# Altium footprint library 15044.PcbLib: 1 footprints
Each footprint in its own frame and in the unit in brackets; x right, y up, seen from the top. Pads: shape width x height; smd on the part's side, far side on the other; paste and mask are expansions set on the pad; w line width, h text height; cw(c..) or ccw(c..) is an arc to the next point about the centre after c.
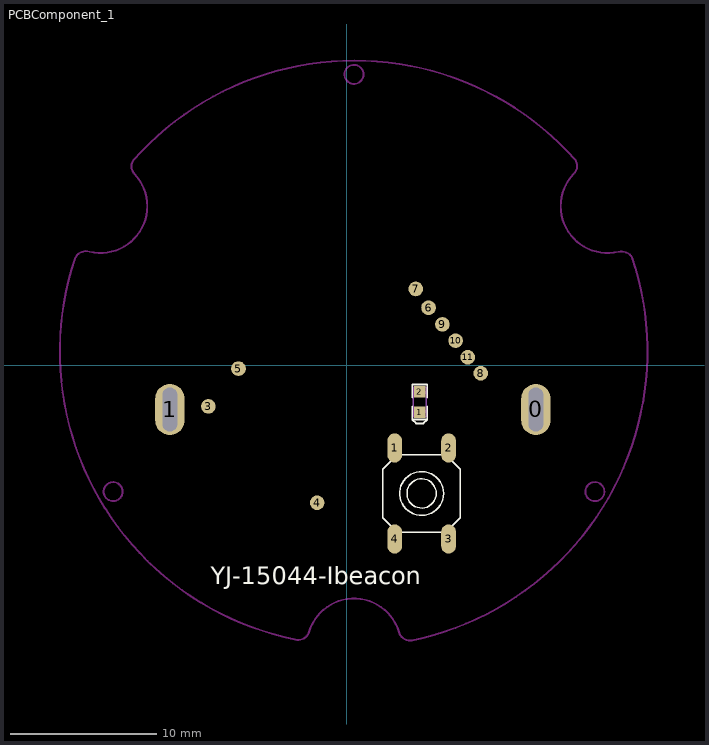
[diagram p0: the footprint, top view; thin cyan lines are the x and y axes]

## PCBComponent_1 [mm]
pads (17):
  oval 2x3.5 hole 1 slot 3 at 90 deg: 0(12.907,-3.027) 1(-12.093,-3.027)
  oval 1x2 smd: 1(3.266,-5.653) 2(6.946,-5.653) 3(6.946,-11.873) 4(3.266,-11.873)
  rect 0.813x0.762 smd: 1(4.978,-3.213) 2(4.978,-1.816)
  round 1 smd: 3(-9.459,-2.817) 4(-2.029,-9.397) 5(-7.402,-0.232) 6(5.578,3.926) 7(4.708,5.206) 8(9.148,-0.554) 9(6.528,2.786) 10(7.428,1.676) 11(8.258,0.536)
Top Overlay:
  circle w0.1: c5.106,-8.763 r1
  circle w0.1: c5.106,-8.763 r1.5
  lines w0.1: 2.456,-10.413 3.456,-11.413 6.756,-11.413 7.756,-10.413 7.756,-7.113 6.756,-6.113 3.456,-6.113 2.456,-7.113 2.456,-10.413
  lines w0.127: 4.47,-2.832 4.47,-3.721 ; 4.47,-2.197 4.47,-1.308 5.486,-1.308 5.486,-2.197 ; 5.486,-2.832 5.486,-3.721 ; 4.47,-3.721 5.486,-3.721 ; 4.47,-3.721 4.724,-3.975 5.232,-3.975 5.486,-3.721
  text "YJ-15044-Ibeacon" at -9.309,-14.967 h1.2
Keep-Out Layer:
  circle w0.127: c-15.967,-8.637 r0.65
  circle w0.127: c0.488,19.863 r0.65
  circle w0.127: c16.942,-8.637 r0.65
  lines w0.127: -14.569,14.023 ccw(c-13.959,13.583) -14.496,13.057 ; -14.568,14.022 cw(c0.521,0.653) 15.593,14.039 cw(c14.981,13.613) 15.481,13.059 ccw(c17.808,10.863) 18.546,7.749 ; -14.506,13.059 cw(c-16.833,10.863) -17.571,7.749 ccw(c-17.819,6.983) -18.572,7.268 ccw(c0.441,0.913) -3.539,-18.735 ; -3.539,-18.737 ccw(c-3.319,-17.997) -2.578,-18.214 ; -2.578,-18.219 cw(c0.488,-19.137) 3.553,-18.219 ccw(c4.331,-18.007) 4.456,-18.803 ccw(c0.351,0.953) 19.487,7.355 ccw(c18.741,6.903) 18.539,7.752
Mechanical 7:
  lines w0.1: 4.54,-3.215 5.417,-3.215 ; 4.54,-3.115 5.417,-3.115 ; 4.54,-1.915 5.417,-1.915 ; 4.54,-1.815 5.417,-1.815 ; 4.54,-3.515 4.54,-1.515 5.417,-1.515 5.417,-3.515 4.54,-3.515
  text "LED_G" at 5.103,-3.015 h0.3
3D body: height 0.6, standoff 0, extent 4.578,-3.318 5.378,-1.698
3D body: height 1, standoff 0, extent 2.439,-11.43 7.773,-6.096
3D body: height 0.2, standoff 0, extent 6.63,-6.604 7.265,-5.207
3D body: height 0.2, standoff 0, extent 2.947,-12.319 3.582,-10.922
3D body: height 0.2, standoff 0, extent 3.074,-6.477 3.582,-5.207
3D body: height 0.2, standoff 0, extent 6.63,-12.319 7.138,-11.049
3D body: height 1.5, standoff 1, extent 4.108,-9.763 6.104,-7.771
